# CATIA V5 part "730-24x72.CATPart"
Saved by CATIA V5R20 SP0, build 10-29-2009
Part number: 730-24x72
Definition: NONE
Nomenclature: 730-24x72
Source: Unknown
Description: 730-24x72
Bounding box of the stored display mesh (mm): x -14.941 to 14.941, y -14.5 to 14.5, z 0 to 72
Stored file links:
  C:\Users\Utente\Desktop\IO LAVORO\3D X SITO CF\X SITO\730\730-24x72.CATPart
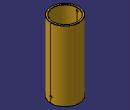
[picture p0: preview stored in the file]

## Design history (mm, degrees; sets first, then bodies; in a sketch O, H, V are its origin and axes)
Body1 "730-24x72" (main body)
  Solid1: solid without history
